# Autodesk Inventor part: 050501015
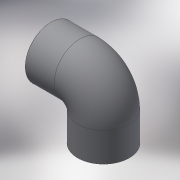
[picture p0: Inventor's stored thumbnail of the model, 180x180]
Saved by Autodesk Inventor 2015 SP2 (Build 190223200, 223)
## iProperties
Created: 2017-10
Part Number: 050501015
Material: Generic
Description: PLASSON THREADED 90° ELBOW PVC 1.1/2"
Document SubType Name: Modeling
Designer: KIM
Density: 1 g/cm^3
Appearance: Default
Author: KIM
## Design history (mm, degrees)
derived "050501.ipt"
feature "Solid1::050501.ipt"
tag "TaggingFeature1"
body "Solid1"
other parameters: "d7" = 0.44845, "d9" = 62, "d10" = 59, "d13" = 90 deg, "d19" = 90 deg, "d20" = 44.845, "d21" = 22, "d22" = 0, "d24" = 90 deg, "d26" = 40.3605, "d27" = 90 deg, "d28" = 22, "G_" = 44.845, "E_" = 62, "lt_" = 22
